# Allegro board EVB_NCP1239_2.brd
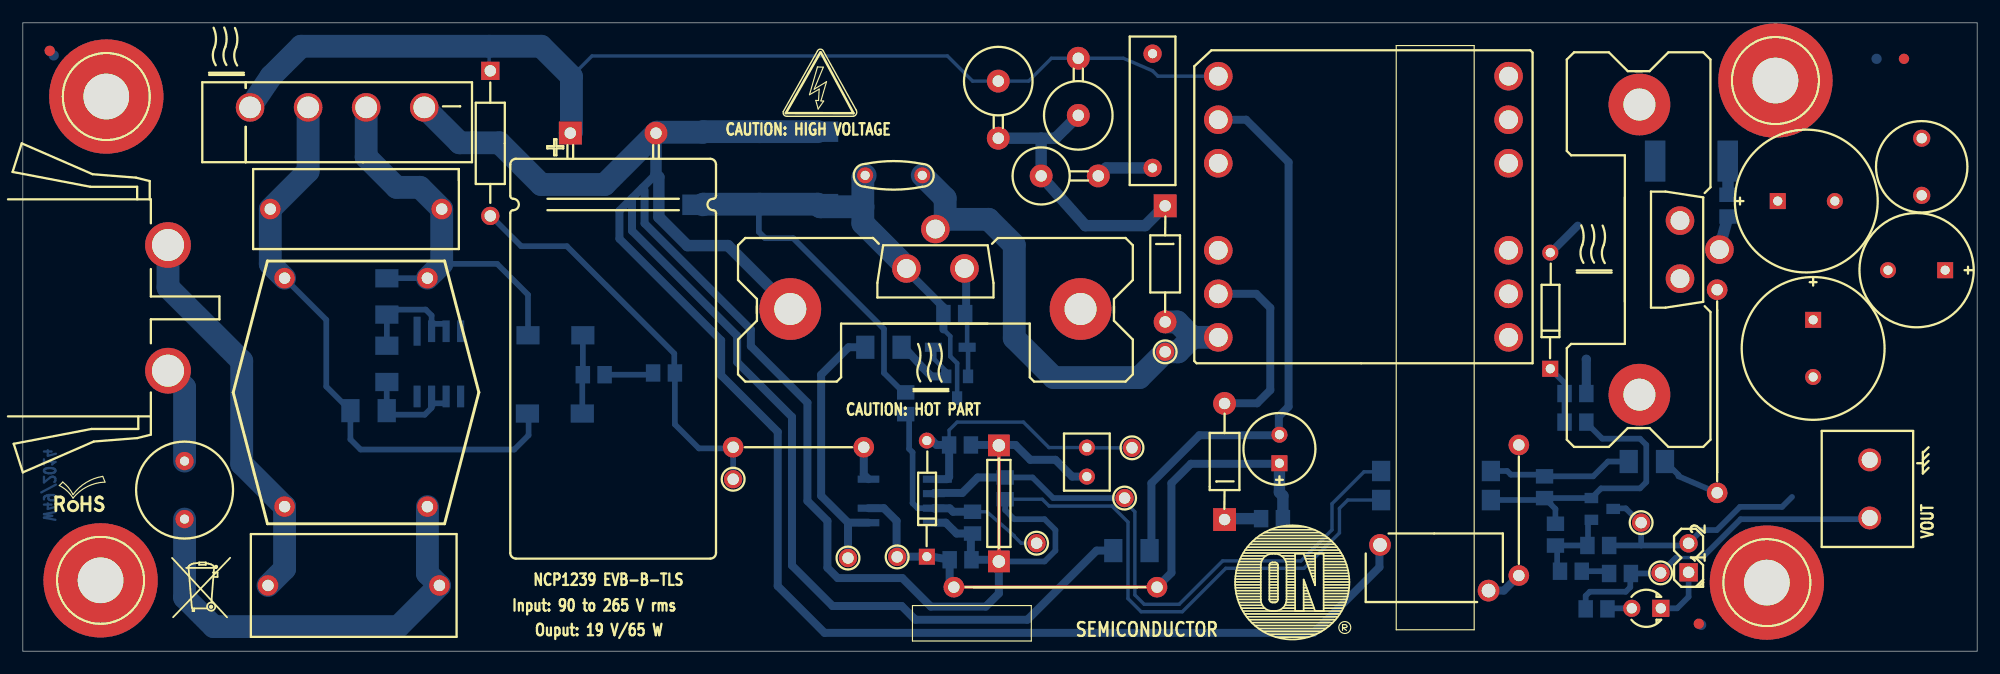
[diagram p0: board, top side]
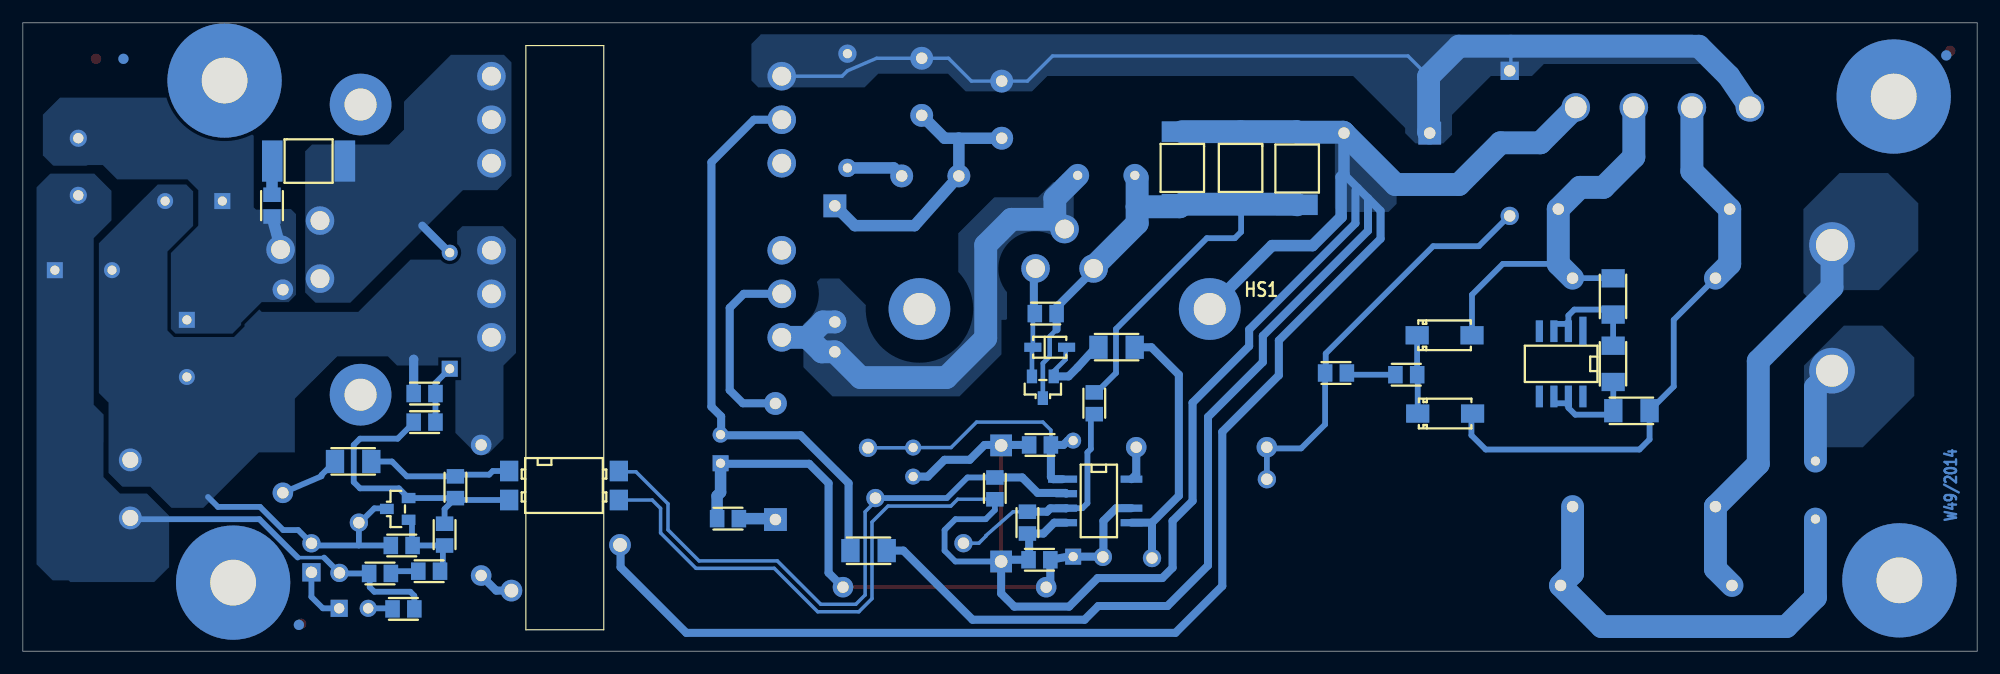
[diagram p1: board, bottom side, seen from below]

Outline 171 x 55 mm; copper layers: TOP, IN1, IN2, BOTTOM. Coordinates in mm from the lower left corner of the outline.
Outline path: 0,55 0,0 171,0 171,55 0,55

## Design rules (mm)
net group HT: nets N12215515 N12215613

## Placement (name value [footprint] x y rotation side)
C1  2.2nF Y1  [CAPA_DISK_E5_D12_P10]  123.5 7.3 0 top
C2  470nF  [CAPA_E9_L18_H17_P15]  28.95 5.75 0 top
C3  220nF  [CAPA_E7_L18_H13_P15]  29.15 38.7 0 top
C4  100uF  [CAPA_CH_D18X35-5P7-5]  51.65 45.35 270 top
C5  10nF  [CAPA_E4_L13_H10_P10]  98.85 47.3 90 top
C6  1nF  [0805]  82 18.05 180 bottom
C7  1nF  [0805]  85.95 14.25 90 bottom
C8  220pF  [0805]  83.1 11.25 90 bottom
C9  100nF  [0805]  82.05 8 0 bottom
C10  47uF  [CAPA_CH_D6-3_H11-5_P2-5]  109.95 17.7 90 top
C11  100pF  [CAPA_DISK_P5]  76.2 41.65 0 top
C12  220pF  [0805]  149.2 39 90 bottom
C13  680uF  [CAPA_CH_D12-5_H20_P5]  156.65 26.5 270 top
C14  680uF  [CAPA_CH_D12-5_H20_P5]  156.05 39.4 0 top
C15  220uF  [CAPA_CH_D10_H13_P5]  165.7 33.35 180 top
C16  47nF  [0805]  134.1 10.2 270 bottom
C18  1nF  [0805]  135.85 22.55 180 bottom
CB1  target_cms  [MIRE_LOW]  162.2 51.85 180 bottom
CB2  target_cms  [MIRE_LOW]  146.85 2.3 180 bottom
CB3  target_cms  [MIRE_LOW]  164.6 51.85 0 top
CB4  target_cms  [MIRE_LOW]  2.35 52.55 0 top
CB5  target_cms  [MIRE_LOW]  2.7 52.15 180 bottom
CB6  target_cms  [MIRE_LOW]  146.65 2.4 0 top
CS  TEST POINT  [TP_T1]  88.7 9.45 0 top
D1  MRA4007T  [DO214AC_SMA_POL]  46.55 20.8 180 bottom
D2  MRA4007T  [DO214AC_SMA_POL]  46.6 27.65 180 bottom
D3  1N4937  [DO41]  99.95 33.9 270 top
D4  1N4937  [DO41]  105.15 16.6 90 top
D5  BZX79-C18  [DO35]  79.1 13.35 90 top
D6  MMSD4148T1  [SOD123]  81.15 26.6 180 bottom
D7  MBR20H200  [TO-220_RAD-SW25-2]  145 35.15 90 top
D8  BAV21  [DO35]  133.65 29.8 90 top
D9  Red LED  [LED_3MM]  142.05 3.75 180 top
DRAIN  TEST POINT  [TP_T1]  99.95 26.2 0 top
DRV  TEST POINT  [TP_T1]  72.2 8.15 0 top
F1  2A/250VAC  [FUSE_D8-5_H8-5_P5]  14.15 14.1 270 top
FB  TEST POINT  [TP_T1]  96.4 13.4 0 top
FIX1  TM  [FIX_HOLE4_D10]  153.35 49.95 0 top
FIX2  TM  [FIX_HOLE4_D10]  6.8 6.2 0 top
FIX3  TM  [FIX_HOLE4_D10]  7.3 48.55 0 top
FIX4  TM  [FIX_HOLE4_D10]  152.6 6 0 top
HS1  SW25-2  [HS]  79.85 29.85 180 bottom
HS2  SW25-2  [HS]  141.5 35.2 90 top
HV  TEST POINT  [TP_T1]  62.15 15.05 0 top
IC1  KBU4K  [PONT_RD_KBU4]  27.5 47.6 180 top
IC2  NCP1239  [SO8_7]  76.85 13.15 180 bottom
IC3  SFH6156-2  [DIP4_SMD]  123.65 14.5 180 bottom
IC4  NCP431  [SOT23]  138.2 12.45 270 bottom
IC5  NCP4810  [SO8]  36.4 25.15 270 bottom
J1  JR201S-PCB  [CON_220V_JR-201S]  12.7 30.05 90 top
J2  PM5.08/2  [CON_BORNIER_2_P508]  161.6 14.2 270 top
J3  JUMPER  [HE14_1X2]  145.75 6.9 90 top
L1  RN114-1.2-02  [SELF_RN114-0_8-02]  29.15 22.65 270 top
L2  1uH  [SELF_WE-TI_D7-8_H10_P5]  166.15 42.4 270 top
LATCH  TEST POINT  [TP_T1]  97.05 17.8 0 top
M1  NDF06N60Z  [TO-220_RAD-SW25-2]  79.85 33.5 180 top
NOREF  -  []  7.3 48.55 90 top
NOREF#2  -  []  -114.15 -45.45 0 top
NOREF#3  -  []  4.7 18.7 0 top
NOREF#4  -  []  -181.6 -72.35 0 top
NOREF#5  -  []  0 55 0 top
NOREF#6  -  []  0 55 0 top
NOREF#7  -  []  0 0 90 top
NOREF#8  -  []  52.5 6.6 0 top
NOREF#9  -  []  283.55 -61.75 180 bottom
Q1  BC857  [SOT23]  81.75 23.1 180 bottom
R1  47k  [RES_3W_D6XL15_JP]  85.35 49.9 270 top
R2  47k  [RES_3W_D6XL15_JP]  92.35 46.9 90 top
R3  22R  [RES_1W_D5XL12]  89.1 41.6 0 top
R4  0R  [MRS25]  40.9 44.45 270 top
R5  2.7K  [0805]  49.95 24.2 180 bottom
R6  2.7K  [0805]  56.1 24.35 180 bottom
R7  NTC  [NTC_D4_P254]  93.1 16.55 90 top
R8  1K6  [0805]  77.25 21.7 270 bottom
R9  10R  [1206]  75.3 26.6 0 bottom
R10  0R  [0805]  109.3 11.6 0 bottom
R11  47k  [0805]  81.5 29.55 180 bottom
R12  1R  [2512]  69.55 42.3 270 bottom
R13  1R  [2512]  59.5 42.25 270 bottom
R14  1R  [2512]  64.45 42.3 270 bottom
R15  33R  [2512]  146 42.9 180 bottom
R16  1K  [1206]  142.1 16.6 0 bottom
R17  10k  [0805]  133.15 14.35 90 bottom
R18  27K  [0805]  139.75 6.8 0 bottom
R19  39K  [0805]  135.45 7 0 bottom
R20  10k  [0805]  137.85 9.25 180 bottom
R21  470K  [1206]  31.85 31.05 270 bottom
R22  470K  [1206]  30.25 21.05 180 bottom
R23  nc  [1206]  31.85 25.15 270 bottom
R24  0R  [1206]  97 8.8 180 bottom
R25  10k  [0805]  135.85 20.05 180 bottom
R26  33K  [0805]  137.7 3.7 0 bottom
S1  Strap  [STRAP_FIL_400]  68.5 17.85 0 top
S2  Strap  [STRAP_FIL_700]  90.35 5.6 0 top
S3  Strap  [STRAP_FIL_400]  130.9 11.7 270 top
S4  Strap  [STRAP_FIL_700]  148.25 22.75 270 top
SGND  TEST POINT  [TP_T1]  141.6 11.25 0 top
ST1  Cav or strap  [JUMPER400H]  85.4 7.85 90 top
T1  PQ2526-1112  [TRANSFO_PQ25]  117.3 38.9 270 top
VCC  TEST POINT  [TP_T1]  76.5 8.25 0 top
VOUT  TEST POINT  [TP_T1]  143.3 6.85 0 top

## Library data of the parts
C1-C3 C5-C9 C12 C16 C18 = C
C4 C13-C15 = C_elect_0
C10 = C_elect_1
C11 = C: tolerance: 10%
CB1-CB6 = target_cms
CS DRAIN DRV FB HV LATCH S1-S4 SGND ST1 VCC VOUT = TEST POINT_0
D1-D4 = D1N4937
D5 = BZX84C24/SOT_0
D6 = MMSD4148T1_1
D7 = dual_diodeAAK
D8 = D1N4937_0
D9 = LED_0
F1 = FUSE
FIX1-FIX4 = TM
HS1 HS2 = Heatsink_KL_196
IC1 = KBUxK_1
IC2 = NCP1239
IC3 = OPTO_0
IC4 = TL431_0
IC5 = NCP4810
J1 = CON_2P_220v
J2 = HEADER 2_1
J3 = JUMPER_0
L1 = RN114-0.8/02
L2 = L
M1 = SPP11N60S5
Q1 = BC857
R1 R2 R4-R6 R8-R11 R15-R26 = R
R3 = R: alternate symbols: (RES_1W_D5XL12_jp)
R7 = VARISTOR
R12-R14 = R: tolerance: 1%
T1 = transfo_PQ2625-1112_0

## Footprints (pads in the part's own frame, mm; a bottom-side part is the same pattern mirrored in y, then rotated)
0805
  rect 1.27x1.524 smd: 1(-0.953,0) 2(0.953,0)
1206
  rect 1.6x2.03 smd: 1(-1.587,0) 2(1.587,0)
2512
  rect 1.8x3.6 smd: 1(-3.175,0) 2(3.175,0)
CAPA_CH_D6-3_H11-5_P2-5
  rect 1.4x1.4 hole 0.8: 1(-1.25,0)
  round 1.4 hole 0.8: 2(1.25,0)
CAPA_CH_D10_H13_P5
  rect 1.4x1.4 hole 0.8: 1(-2.5,0)
  round 1.4 hole 0.8: 2(2.5,0)
CAPA_CH_D12-5_H20_P5
  rect 1.4x1.4 hole 0.8: 1(-2.5,0)
  round 1.4 hole 0.8: 2(2.5,0)
CAPA_CH_D18X35-5P7-5
  rect 2x2 hole 1: 1(0,-3.75)
  round 2 hole 1: 2(0,3.75)
CAPA_DISK_E5_D12_P10
  round 1.9 hole 1.2: 1(-4.75,2) 2(4.75,-2)
CAPA_DISK_P5
  round 1.4 hole 0.8: 1(-2.5,0) 2(2.5,0)
CAPA_E4_L13_H10_P10
  round 1.6 hole 0.8: 1(-5,0) 2(5,0)
CAPA_E7_L18_H13_P15
  round 1.8 hole 1: 1(7.5,0) 2(-7.5,0)
CAPA_E9_L18_H17_P15
  round 1.8 hole 1: 1(7.5,0) 2(-7.5,0)
CON_220V_JR-201S
  round 4 hole 2.8: 1(5.5,0) 2(-5.5,0)
CON_BORNIER_2_P508
  round 2 hole 1.4: 1(-2.54,0) 2(2.54,0)
DIP4_SMD
  rect 1.6x1.8 smd: 1(-4.8,1.27) 2(-4.8,-1.27) 3(4.8,-1.27) 4(4.8,1.27)
DO35
  rect 1.4x1.4 hole 0.8: 1(-5.08,0)
  round 1.4 hole 0.8: 2(5.08,0)
DO41
  round 2 hole 1: 1(5.08,0)
  rect 2x2 hole 1: 2(-5.08,0)
DO214AC_SMA_POL
  rect 2.03x1.6 smd: 1(2.4,0) 2(-2.4,0)
FIX_HOLE4_D10
  round 10 hole 4: 1(0,0)
FUSE_D8-5_H8-5_P5
  round 1.6 hole 0.8: 1(2.54,0) 2(-2.54,0)
HE14_1X2
  rect 1.6x1.6 hole 1: 1(0,0)
  round 1.6 hole 1: 2(2.54,0)
HS
  round 0.3 smd: 1(-12.7,0) 2(12.7,0)
JUMPER400H
  rect 1.9x1.9 hole 1.1: 1(0,0) 2(10.16,0)
LED_3MM
  round 1.5 hole 0.9: A(1.27,0)
  rect 1.5x1.5 hole 0.9: K(-1.27,0)
MIRE_LOW
  round 0.9 smd: 1(0,0)
MRS25
  rect 1.6x1.6 hole 1: 1(-6.35,0)
  round 1.6 hole 1: 2(6.35,0)
NTC_D4_P254
  round 1.4 hole 0.8: 1(1.27,0) 2(-1.27,0)
PONT_RD_KBU4
  round 2.5 hole 1.9: 1(7.62,0) 2(2.54,0) 3(-2.54,0) 4(-7.62,0)
RES_1W_D5XL12
  round 2 hole 1: 1(0,0) 2(5,0)
RES_3W_D6XL15_JP
  round 2 hole 1: 1(0,0) 2(5,0)
SELF_RN114-0_8-02
  round 1.8 hole 1: 1(-10,6.25) 2(-10,-6.249) 3(9.997,-6.249) 4(9.997,6.25)
SELF_WE-TI_D7-8_H10_P5
  round 1.5 hole 0.9: 1(-2.5,0) 2(2.5,0)
SO8
  rect 2.54x0.63 smd: 1(-2.857,1.905)
  rect 1.9x0.63 smd: 2(-2.855,0.635) 3(-2.855,-0.635) 4(-2.855,-1.905) 5(2.855,-1.905) 6(2.855,-0.635) 7(2.855,0.635) 8(2.855,1.905)
SO8_7
  rect 2.54x0.63 smd: 1(-3.172,1.905)
  rect 1.9x0.63 smd: 2(-2.855,0.635) 3(-2.855,-0.635) 4(-2.855,-1.905) 5(2.855,-1.905) 6(2.855,-0.635) 8(2.855,1.905)
SOD123
  rect 1.5x0.8 smd: 1(1.475,0) 2(-1.475,0)
SOT23
  rect 0.9x1.2 smd: 1(0.953,0.953) 2(-0.953,0.953) 3(0,-0.953)
STRAP_FIL_400
  round 1.8 hole 1: 1(-6.35,0) 2(5.08,0)
STRAP_FIL_700
  round 1.8 hole 1: 1(-8.89,0) 2(8.89,0)
TO-220_RAD-SW25-2
  round 5.4 hole 2.8: (-12.7,3.55) (12.7,3.55)
  round 2.5 hole 1.65: 1(-2.54,0) 2(0,-3.45) 3(2.54,0)
TP_T1
  round 1.6 hole 1: 1(0,0)
TRANSFO_PQ25
  round 2.5 hole 1.65: 1(-11.43,-12.7) 2(-7.62,-12.7) 3(-3.81,-12.7) 4(3.81,-12.7) 5(7.62,-12.7) 6(11.43,-12.7) 7(11.43,12.7) 8(7.62,12.7) 9(3.81,12.7) 10(-3.81,12.7) 11(-7.62,12.7) 12(-11.43,12.7)

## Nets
GND_EARTH: C13.2(-) C14.2(-) C15.2(-) C18.1 IC4.3(A) J2.1 J3.2 R20.1 S3.1 SGND.1 T1.7 T1.8 T1.9
GND_MECA1: FIX1.1(TM)
GND_MECA2: FIX2.1(TM)
GND_MECA3: FIX3.1(TM)
GND_MECA4: FIX4.1(TM)
VCC: C9.1 C10.1(+) D5.1(CATHODE) IC2.6(VCC) R10.2 S2.1 S2.2 VCC.1
VIN: C4.1(+) C5.2 IC1.1(+) R1.1 R2.2 R4.1 T1.1
0: C1.1 C4.2(-) C6.1 C7.1 C8.1 C9.2 HS1.2 IC1.4(-) IC2.4(GND) IC3.3 R7.2 R12.1 R13.1 R14.1 R24.2 ST1.1 ST1.2
MID: T1.3
VAUX: D4.1 T1.5
VOUT: C15.1(+) J2.2 L2.2 R18.2 R26.1 VOUT.1
N3314386: C16.2 IC4.1(REF) R19.1 R20.2
N3314440: C16.1 IC3.2 IC4.2(K) R17.1 R25.1
N3314452: C10.2(-) R24.1 T1.2
N3314486: IC3.1 R16.1 R17.2
N3314708: R18.1 R19.2
N3316204: C12.1 C13.1(+) C14.1(+) D7.2(C) L2.1 S4.1
N3316264: D7.1(A1) D7.3(A2) D8.2 R15.2 T1.10 T1.11 T1.12
N3316344: C11.2 D3.1 DRAIN.1 M1.2(D) T1.6
N3316348: C12.2 R15.1
N12209171: F1.2 J1.2
N12209175: C2.2 J1.1 L1.3
N12209179: C2.1 F1.1 L1.4
N12212886: C3.2 D1.1 IC1.2(AC1) L1.2 R22.2
N12212902: IC5.6(AC4) IC5.7(AC3) R22.1 R23.2
N12212919: IC5.2(AC1) IC5.3(AC2) R21.2 R23.1
N12212937: C3.1 D2.1 IC1.3(AC2) L1.1 R21.1
N12213264: D1.2 D2.2 R5.2
N12215515: D3.2 R1.2 R2.1 R3.1
N12215613: C5.1 R3.2
N12216524: D6.1(A) Q1.1(BASE) R9.2
N12216532: D6.2(C) M1.1(G) Q1.2(EMITTER) R11.1
N12216556: C11.1 M1.3(S) Q1.3(COLLECTOR) R8.1 R11.2 R12.2 R13.2 R14.2
N12217807: DRV.1 IC2.5(DRV) R9.1
N12221043: R16.2 S4.2
N12222218: HV.1 R4.2 R6.1 S1.1
N12222571: IC2.8(HV) S1.2
N12222631: C8.2 CS.1 IC2.3(CS) R8.2
N12222819: C6.2 D5.2(ANODE) IC2.1(LATCH) LATCH.1 R7.1
N12223425: C7.2 FB.1 IC2.2(FB) IC3.4
N12246258: C1.2 S3.2
N12256702: C18.2 D8.1 R25.2
N122152181: R5.1 R6.2
N122157731: D4.2 R10.1
N122564260: D9.A(ANODE) R26.2
N122564261: D9.K(CATHODE) J3.1

Pads without a net: CB1 1; CB2 1; CB3 1; CB4 1; CB5 1; CB6 1; HS1 1; HS2 1 2; IC5 1 4 5 8; T1 4

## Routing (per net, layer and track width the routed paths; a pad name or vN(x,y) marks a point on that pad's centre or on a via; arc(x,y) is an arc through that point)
GND_EARTH: length 25.7
  BOTTOM w0.5: 141.6,9.25 145.56,9.25 J3.2 146.91,10.6 148.22,10.6 150.25,12.63 153.93,12.63 154.8,13.5 ; 141.6,9.25 R20.1 ; 141.6,9.25 SGND.1 141.5,11.25 140.25,12.5 139.2,12.5 IC4.3
  BOTTOM w0.8: C18.1 136.8,25.55 136.8,25.55
VCC: length 55.8
  TOP w0.3: S2.1 S2.2
  BOTTOM w0.7: S2.2 100.5,6.86 100.5,14.7 102.2,16.4 109.9,16.4 C10.1 ; S2.1 81.1,5.96 C9.1 79.58,8.27 D5.1 76.52,8.27 VCC.1 76.45,8.3 76.45,11.4 75.33,12.52 74,12.52
  BOTTOM w1: C10.1 109.95,13.9 110.25,13.6 R10.2
VIN: length 98.4
  BOTTOM w0.3: R4.1 40.8,50.9 40.8,52.95 ; T1.1 99.32,50.33 98.85,50.8 96.3,51.9 R2.2 90,51.9 88,49.9 R1.1 83.1,49.9 80.9,52.1 49.8,52.1 48,50.3
  BOTTOM w2: C4.1 48,45.45 48,50.3 45.35,52.95 24.35,52.95 21.73,50.33 IC1.1
0: length 383.1
  TOP w0.3: ST1.1 ST1.2
  BOTTOM w0.3: IC3.3 115.93,13.23 115.2,12.5 115.2,10.35 112.1,7.25 105.25,7.25 101.45,3.45 97.85,3.45 96.7,4.6 96.7,11.3 95.3,12.7 89.8,12.7 89.2,13.3 85.95,13.3 C7.1
  BOTTOM w0.5: ST1.1 89.4,7.85 90.35,8.8 90.35,10.6 89.4,11.55 86.75,11.55 85.95,12.35 C7.1 ; 54.2,40.55 54.4,40.35
  BOTTOM w0.7: 53.3,39.65 52.2,38.55 52.2,36.1 61.1,27.2 61.1,24.15 66.05,19.2 66.05,5.7 70.15,1.6 112.95,1.6 118.7,7.35 118.7,9.25 C1.1 ; 53.3,39.65 55.4,41.75 ; 53.3,39.65 53.3,36.8 62.5,27.6 62.5,25.3 67.3,20.5 67.3,7.5 70.85,3.95 76.9,3.95 78.1,2.75 87.9,2.75 93.95,8.8 R24.2 ; R7.2 91.82,15.28 90.35,16.75 88.15,16.75 86.85,18.05 85.44,18.05 ST1.2 85.36,18.05 C6.1 ; 54.4,40.35 54.4,37.45 63.7,28.15 63.7,26.7 68.65,21.75 68.65,13.15 70.4,11.4 70.4,7.3 71.3,6.4 76.95,6.4 79.45,3.9 84.25,3.9 85.4,5.05 ST1.1 85.25,8 C9.2 82.95,8.05 82.95,10.3 ; 82.95,10.3 81.7,10.3 80.75,11.24 79.7,11.24 ; 82.95,10.3 C8.1
  BOTTOM w1: C4.2 55.4,41.75 55.65,41.5 55.65,38 58.15,35.5 61.7,35.5 67.15,30.05 HS1.2
  BOTTOM w2: 69.55,45.48 59.55,45.48 R13.1 55.48,45.42 C4.2 50.9,40.85 45.35,40.85 41.7,44.5 38.22,44.5 IC1.4
VAUX: length 16.7
  BOTTOM w0.7: D4.1 105.17,21.7 108,21.7 109.15,22.85 109.15,30.05 107.92,31.28 T1.5
VOUT: length 29.5
  BOTTOM w0.3: 144.64,8.19 146.94,8.19 146.95,8.2
  BOTTOM w0.5: R26.1 136.75,4.85 137.1,5.2 140.25,5.2 140.65,5.6 140.65,6.75 R18.2 143.25,6.8 VOUT.1 144.64,8.19 ; 146.95,8.2 150.3,11.55 161.49,11.55 J2.2
N3314386: length 7.7
  BOTTOM w0.5: IC4.1 137.15,11.5 136.95,11.3 136.95,9.3 R20.2 134.1,9.25 C16.2 134.25,9.1 134.25,7.25 R19.1
N3314440: length 26.2
  BOTTOM w0.5: R25.1 136.8,20 138.2,18.6 141.5,18.6 142.05,18.05 142.05,14.8 141.5,14.25 138.09,14.25 IC4.2 133.16,13.4 R17.1 ; R17.1 132.98,13.23 IC3.2 ; R17.1 134.1,12.45 C16.1
N3314452: length 50.8
  BOTTOM w0.7: T1.2 107.03,46.52 110.75,42.8 110.75,21.4 109.9,20.55 109.9,19 C10.2 109.9,18.9 102.95,18.9 98.75,14.7 98.75,8.96 R24.1
N3314486: length 12.8
  BOTTOM w0.5: IC3.1 129.88,15.77 130.2,15.45 133,15.45 R17.2 137.4,15.3 138.7,16.6 R16.1
N3314708: length 2.5
  BOTTOM w0.5: R18.1 138.6,7 R19.2
N3316204: length 3.1
  BOTTOM w1: C12.1 148.4,35.1 D7.2
N3316264: length 3.4
  BOTTOM w0.7: D8.2 133.68,34.88 136.05,37.25
N3316344: length 44.7
  BOTTOM w2: 80.7,37.8 80.7,39.65 C11.2 ; 80.7,37.8 M1.2 ; 80.7,37.8 84.5,37.8 86.75,35.55 86.75,27.4 90.2,23.95 97.7,23.95 DRAIN.1 101.08,26.2 102.35,27.47 ; D3.1 101,28.82 102.35,27.47 ; T1.6 102.35,27.47
N3316348: length 3
  BOTTOM w1: R15.1 149.2,42.88 C12.2
N12209171: length 8.5
  BOTTOM w2: J1.2 14.15,23.1 F1.2
N12209175: length 34.6
  BOTTOM w2: C2.2 22.9,7.2 L1.3 22.9,12.65 19.15,16.4 19.15,25.4 12.7,31.85 J1.1
N12209179: length 39
  BOTTOM w2: F1.1 14.15,4.7 16.7,2.15 32.85,2.15 C2.1 35.4,6.8 L1.4
N12212886: length 51.8
  BOTTOM w0.5: D1.1 44.25,20.7 44.25,18.9 43,17.65 29.55,17.65 28.66,18.54 R22.2 26.55,23.16 26.55,29 L1.2
  BOTTOM w2: L1.2 21.65,33.9 C3.2 24.96,42.01 IC1.2
N12212902: length 9.6
  BOTTOM w0.5: 35.77,21.7 35.77,21.3 35.16,20.7 32.19,20.7 R22.1 31.84,23.55 R23.2 ; 35.77,21.7 35.77,22.3 ; 35.77,21.7 36.94,21.7 37.03,21.8 37.03,22.3
N12212919: length 10.2
  BOTTOM w0.5: IC5.3 37.03,28.57 36.95,28.65 35.77,28.65 ; 35.77,28.65 35.77,29.39 35.25,29.9 32.79,29.9 R21.2 R23.1 ; 35.77,28.65 IC5.2
N12212937: length 35.2
  BOTTOM w0.5: D2.1 44.2,31.2 41.5,33.9 36.65,33.9 ; L1.1 32.36,32.65 R21.1
  BOTTOM w2: IC1.3 30.04,43.26 32.7,40.6 34.75,40.6 C3.1 36.65,33.9 L1.1
N12213264: length 6.9
  BOTTOM w0.5: D2.2 49,24.2 R5.2 48.95,24.15 D1.2
N12215515: length 24.6
  BOTTOM w1: 89.1,44.9 R1.2 ; 89.1,44.9 90.35,44.9 R2.1 ; 89.1,44.9 R3.1 92.97,37.25 98.2,37.25 99.93,38.98 D3.2
N12215613: length 5
  BOTTOM w1: C5.1 94.8,42.3 R3.2
N12216524: length 8
  BOTTOM w0.4: D6.1 79.75,26.52 79.75,25.55 80.8,24.5 Q1.1
  BOTTOM w0.7: R9.2 77.11,26.6 78.7,24.85 79.5,24.05 Q1.1
N12216532: length 9.7
  BOTTOM w0.4: Q1.2 82.7,26.52 D6.2 82.62,29.26 82.54,29.35
  BOTTOM w0.7: 82.54,29.64 R11.1 ; 82.54,29.64 82.54,33.35 M1.1 ; 82.54,29.64 82.54,29.35
N12216556: length 60.5
  BOTTOM w0.4: 80.55,28.16 81.15,27.56 81.15,25.8 81.75,25.2 Q1.3
  BOTTOM w0.5: R8.1 77.05,22.65 75.35,24.35 75.35,28.2 67.4,36.15 64.95,36.15 64.4,36.7 64.4,39.08 R14.2
  BOTTOM w0.7: M1.3 77.31,33.34 80.55,30.1 R11.2 80.55,28.16
  BOTTOM w2: 73.5,38.9 73.5,41.45 C11.1 ; 73.5,38.9 73.5,37.45 77.31,33.64 M1.3 ; 73.5,38.9 69.78,38.9 R12.2 R14.2 59.55,39.12 R13.2
N12217807: length 23.7
  BOTTOM w0.7: 74,11.24 72.19,11.24 72.2,11.25 ; R9.1 72.25,26.6 69.85,24.2 69.85,13.6 72.2,11.25 ; 72.2,11.25 DRV.1
N12221043: length 5.5
  BOTTOM w0.5: S4.2 144.87,15.31 144.87,15.42 R16.2
N12222218: length 36.1
  BOTTOM w0.5: R4.2 40.95,38.1 43.6,35.45 47.6,35.45 57,26.05 57,24.4 R6.1 57.05,19.85 59.15,17.75 62.05,17.75 S1.1 HV.1
N12222571: length 3
  BOTTOM w0.7: 74,15.05 73.58,15.47 S1.2
N12222631: length 20.3
  BOTTOM w0.3: CS.1 87.35,9.45 86.75,10.05 86.75,10.1 84.35,12.2 C8.2
  BOTTOM w0.5: IC2.3 78.28,12.52 77.85,12.95 77.85,17.4 77.55,17.7 77.55,20.45 R8.2
  BOTTOM w0.7: C8.2 81.4,12.2 81.1,12.5 79.72,12.5 IC2.3
N12222819: length 24.5
  BOTTOM w0.3: C6.2 81.05,19.35 81.75,20.05 87.55,20.05 89.78,17.82 R7.1 93.12,17.8 LATCH.1
  BOTTOM w0.7: IC2.1 80.85,15.05 81.05,15.25 C6.2 79.95,18.05 79.57,18.43 D5.2
N12223425: length 55.1
  BOTTOM w0.3: 96.1,13.4 97.3,12.2 97.3,4.92 98.12,4.1 101.18,4.1 104.98,7.9 111.83,7.9 114.55,10.62 114.55,12.9 117.35,15.7 118.78,15.7 IC3.4
  BOTTOM w0.5: FB.1 90.15,13.4 88.35,15.2 C7.2
  BOTTOM w0.7: C7.2 83.55,15.2 82.2,13.85 79.77,13.85 IC2.2
N12246258: length 3.2
  BOTTOM w0.7: S3.2 129.58,5.3 C1.2
N12256702: length 5.2
  BOTTOM w0.5: D8.1 134.9,23.47 C18.2 R25.2
N122152181: length 4.3
  BOTTOM w0.5: R6.2 55,24.2 R5.1
N122157731: length 3.2
  BOTTOM w1: R10.1 105.23,11.6 D4.2
N122564260: length 2.1
  BOTTOM w0.5: D9.A 138.7,3.75 R26.2
N122564261: length 5
  BOTTOM w0.5: D9.K 144.75,3.75 145.75,4.75 J3.1

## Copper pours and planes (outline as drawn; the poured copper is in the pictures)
GND_EARTH on BOTTOM: 132.55,37.2 129,37.2 127.85,36.05 127.85,26.1 128.95,25 128.95,18.6 130.25,17.3 131.35,17.3 133.15,19.1 133.15,24.05 134.1,25 138.25,25 139.05,25.8 143.5,25.8 147.2,22.1 147.2,17.4 150.35,17.4 155.2,12.55 158,12.55 159.85,14.4 162.3,14.4 163.5,15.6 163.5,21.75 164.35,22.6 164.35,35.7 159.2,40.85 156.7,40.85 156.1,40.25 156.1,30.6 155.55,30.05 150.5,30.05 150.55,30.1 150.55,30.15 150.1,29.7 141.65,29.7 137.07,34.27 133.72,34.27 133,35 133,36.75
VIN on BOTTOM: 46.7,44.45 45.95,45.2 45.95,46.95 42.55,50.35 38.95,50.35 37.95,51.35 37.95,51.4 23.65,51.4 23.05,52 23.05,52.15 24.9,54 106.45,54 106.45,53.95 107.25,53.15 107.25,49.95 106.65,49.35 97.35,49.35 96.15,50.55 90.05,50.55 88.5,49 82.7,49 81.35,50.35 54.6,50.35 50.05,45.8 50.05,45.35 49.15,44.45
0 on BOTTOM: 54.75,44.95 50.8,41 50.8,39.15 51.5,38.45 55.85,38.45 56.2,38.8 56.2,45.75 55.2,45.75 54.75,45.3
Net_61 on IN2: -4,1 -4,54 174.95,54 174.95,1
VOUT on BOTTOM: 159.5,6.05 158.2,7.35 158.2,11.85 160.15,13.8 162.5,13.8 163.95,15.25 163.95,18.25 163.94,18.26 163.94,20.71 164.8,21.58 164.8,36.15 163.25,37.7 163.25,40.3 164.75,41.8 168.6,41.8 169.8,40.6 169.8,13.3 169.8,7.6 168.4,6.2 167,6.2 166.85,6.05
N3316204 on BOTTOM: 156.6,41.3 155.65,40.35 155.65,37.25 158.05,34.85 158.05,28.2 157.65,27.8 152.65,27.8 151.9,28.55 151.9,28.75 150.1,30.55 147.75,30.55 147.1,31.2 147.1,38.25 147.55,38.7 148.95,38.7 149,38.65 150.6,38.65 150.8,38.85 150.8,46.25 153,48.45 167.75,48.45 169.25,46.95 169.25,43.35 169.2,43.35 168.35,42.5 165.4,42.5 165.35,42.55 164,42.55 162.75,41.3
N3316264 on BOTTOM: 133.55,52.2 128.9,52.2 128.25,51.55 128.25,41.6 129.5,40.35 132.5,40.35 142.35,30.5 145.4,30.5 146.3,31.4 146.3,43.75 145.7,44.35 138.95,44.35 137.65,45.65 137.65,48.1
N3316344 on BOTTOM: 89.15,36.58 89.15,31.75 90.8,30.1 97.05,30.1 99.58,32.62 101.22,32.62 102.7,31.15 102.7,24.85 100.15,22.3 89.05,22.3 84.3,27.05 84.3,33.25 84.25,33.3 84.25,35.2 83.4,36.05 79.65,36.05 79.05,36.65 79.05,40.55 79.55,41.05 80.85,41.05 82.17,39.73 86,39.73
N12209171 on BOTTOM: 15.15,17.9 15.15,25 11.65,28.5 8.3,28.5 5.5,25.7 5.5,22.35 10,17.85 15.1,17.85
N12209175 on BOTTOM: 13.5,29.65 13.5,29.7 11.6,31.6 8.6,31.6 5.15,35.05 5.15,39.2 7.8,41.85 12.05,41.85 15.2,38.7 15.2,31.35

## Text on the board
BOTTOM: BOT 1/2 | W49/2014
Ref Des/Silkscreen Bottom: SILK_BOT
User.Comments: VE_BOT | VE_TOP
TOP: TOP 2/2
Ref Des/Silkscreen Top: Input: 90 to 265 V rms | NCP1239 EVB-B-TLS | Ouput: 19 V/65 W | CAUTION: HIGH VOLTAGE | CAUTION: HOT PART | VOUT | SILK_TOP | SEMICONDUCTOR
IN1: IN1 3/4
IN2: IN2 2/4
DIMENSION: 2.0 | W49/2014 | COLLE
ASSEMBLY_BOTTOM: W49/2014 | 2.0
User.9: CHEMICAL NiAu | 70um(2oz)at START | THICKNESS | MATERIAL | STACKUP | FINISH | SILKSCREEN | MINIMAL GAP | MINIMAL SLIVER | BOARD THICKNESS | SOLDER MASK | COPPER THICKNESS | MARKED ON BOTTOM SOLDERMASK | ALL BOARD ELECTRICALLY TESTED | MANUFACTURE 'S LOGO & DATECODE | COMPLIANT RoHS DIRECTIVE 2011/65/UE | SF /1LAYERS | WHITE TOP&BOT | FR4 IMPROVED (low CTE) | GREEN BOT | 210um /8.0mils | 1.6mm /63mils | 2.0 | W49/2014 | SPEC:
User.10: DEMO NCP1239 1412-1628   W49/2014
User.11: FIGURE | SIZE | 0.8 | 0.9 | 1.0 | 1.1 | 1.2 | 1.4 | 1.65 | 1.9 | 2.8 | 4.0 | DRILL CHART: TOP to BOTTOM | ALL UNITS ARE IN MILLIMETERS | PLATED | QTY | 20 | 4 | 41 | 2 | 18 | 6
